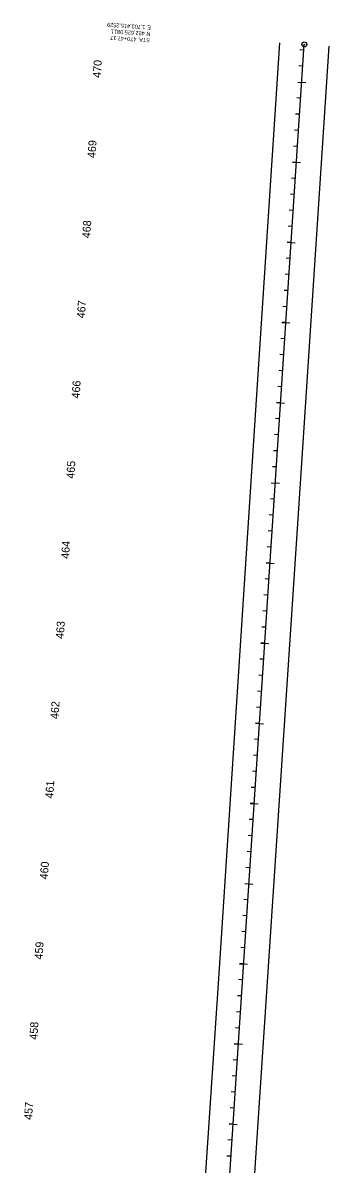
# Model space of a CAD drawing. Extents: x 1699999 to 1705087, y 475568 to 482652.
# Drawn here: x 1703065 to 1703446, y 481231 to 482652 of the extents above; entities that cross this region are included whole.
import ezdxf

# ---------------------------------------------------------------- set-up
doc = ezdxf.new("R2010")
doc.units = 0
for name, color, linetype in [('Default', 7, 'Continuous'), ('DES - DTM - Ground', 7, 'Continuous'), ('DES - DTM - Points - High', 7, 'Continuous'), ('DESIGN - TYPICAL - Guardrail', 7, 'Continuous'), ('TC_Aggregate', 7, 'Continuous')]:
    doc.layers.add(name, color=color, linetype=linetype)

msp = doc.modelspace()

# ---------------------------------------------------------------- linework, layer by layer
at = {"layer": 'Default'}
msp.add_line((1703065.1, 477316.2), (1703415.3, 482625.1), dxfattribs=at)
at = {"layer": 'DES - DTM - Ground'}
msp.add_line((1703065.1, 477316.2), (1703415.3, 482625.1), dxfattribs=at)
for points in [[(1703182.2, 479545.9), (1703224.8, 480202.3), (1703257.7, 480700.5), (1703309.7, 481474.6), (1703350.7, 482106.4), (1703384.7, 482627.1)], [(1703259.7, 479798.3), (1703310.9, 480575.7), (1703327.5, 480825.1), (1703410, 482072.1), (1703446.2, 482623)]]:
    msp.add_lwpolyline(points, dxfattribs=at)
at = {"layer": 'DES - DTM - Points - High'}
for p, q in [((1703414.8, 482617.9), (1703409.8, 482618.3)), ((1703413.5, 482598), (1703408.5, 482598.3)), ((1703407.2, 482578.3), (1703417.1, 482577.7)), ((1703410.8, 482558.1), (1703405.9, 482558.4)), ((1703409.5, 482538.1), (1703404.5, 482538.4)), ((1703408.2, 482518.1), (1703403.2, 482518.5)), ((1703406.9, 482498.2), (1703401.9, 482498.5)), ((1703400.6, 482478.6), (1703410.6, 482477.9)), ((1703404.2, 482458.3), (1703399.3, 482458.6)), ((1703402.9, 482438.3), (1703398, 482438.6)), ((1703401.6, 482418.4), (1703396.6, 482418.7)), ((1703400.3, 482398.4), (1703395.3, 482398.7)), ((1703394, 482378.8), (1703404, 482378.1)), ((1703397.7, 482358.5), (1703392.7, 482358.8)), ((1703396.4, 482338.5), (1703391.4, 482338.9)), ((1703395, 482318.6), (1703390.1, 482318.9)), ((1703393.7, 482298.6), (1703388.7, 482298.9)), ((1703387.4, 482279), (1703397.4, 482278.3)), ((1703391.1, 482258.7), (1703386.1, 482259)), ((1703389.8, 482238.7), (1703384.8, 482239.1)), ((1703388.5, 482218.8), (1703383.5, 482219.1)), ((1703387.1, 482198.8), (1703382.2, 482199.2)), ((1703380.8, 482179.2), (1703390.8, 482178.5)), ((1703384.5, 482158.9), (1703379.5, 482159.2)), ((1703383.2, 482139), (1703378.2, 482139.3)), ((1703381.9, 482119), (1703376.9, 482119.3)), ((1703380.6, 482099.1), (1703375.6, 482099.4)), ((1703374.2, 482079.4), (1703384.2, 482078.8)), ((1703377.9, 482059.1), (1703373, 482059.5)), ((1703376.6, 482039.2), (1703371.6, 482039.5)), ((1703375.3, 482019.2), (1703370.3, 482019.6)), ((1703374, 481999.3), (1703369, 481999.6)), ((1703367.7, 481979.6), (1703377.6, 481979)), ((1703371.3, 481959.4), (1703366.4, 481959.7)), ((1703370, 481939.4), (1703365.1, 481939.7)), ((1703368.7, 481919.4), (1703363.7, 481919.8)), ((1703367.4, 481899.5), (1703362.4, 481899.8)), ((1703361.1, 481879.9), (1703371.1, 481879.2)), ((1703364.8, 481859.6), (1703359.8, 481859.9)), ((1703363.4, 481839.6), (1703358.5, 481839.9)), ((1703362.1, 481819.7), (1703357.2, 481820)), ((1703360.8, 481799.7), (1703355.8, 481800)), ((1703354.5, 481780.1), (1703364.5, 481779.4)), ((1703358.2, 481759.8), (1703353.2, 481760.1)), ((1703356.9, 481739.8), (1703351.9, 481740.2)), ((1703355.5, 481719.9), (1703350.6, 481720.2)), ((1703354.2, 481699.9), (1703349.3, 481700.2)), ((1703347.9, 481680.3), (1703357.9, 481679.6)), ((1703351.6, 481660), (1703346.6, 481660.3)), ((1703350.3, 481640), (1703345.3, 481640.4)), ((1703349, 481620.1), (1703344, 481620.4)), ((1703347.6, 481600.1), (1703342.7, 481600.5)), ((1703341.3, 481580.5), (1703351.3, 481579.8)), ((1703345, 481560.2), (1703340, 481560.6)), ((1703343.7, 481540.3), (1703338.7, 481540.6)), ((1703342.4, 481520.3), (1703337.4, 481520.6)), ((1703341.1, 481500.4), (1703336.1, 481500.7)), ((1703334.8, 481480.7), (1703344.7, 481480.1)), ((1703338.4, 481460.4), (1703333.5, 481460.8)), ((1703337.1, 481440.5), (1703332.1, 481440.8)), ((1703335.8, 481420.5), (1703330.8, 481420.9)), ((1703334.5, 481400.6), (1703329.5, 481400.9)), ((1703328.2, 481380.9), (1703338.2, 481380.3)), ((1703331.8, 481360.7), (1703326.9, 481361)), ((1703330.5, 481340.7), (1703325.6, 481341)), ((1703329.2, 481320.7), (1703324.2, 481321.1)), ((1703327.9, 481300.8), (1703322.9, 481301.1)), ((1703321.6, 481281.2), (1703331.6, 481280.5)), ((1703325.3, 481260.9), (1703320.3, 481261.2)), ((1703323.9, 481240.9), (1703319, 481241.2))]:
    msp.add_line(p, q, dxfattribs=at)
at = {"layer": 'DESIGN - TYPICAL - Guardrail'}
for p, q in [((1703407.2, 482578.3), (1703417.2, 482577.7)), ((1703405.6, 482478.2), (1703400.6, 482478.6)), ((1703399, 482378.4), (1703394, 482378.8)), ((1703392.4, 482278.7), (1703387.4, 482279)), ((1703385.8, 482178.9), (1703380.8, 482179.2)), ((1703374.2, 482079.4), (1703384.2, 482078.8)), ((1703372.7, 481979.3), (1703367.7, 481979.6)), ((1703366.1, 481879.5), (1703361.1, 481879.9)), ((1703359.5, 481779.7), (1703354.5, 481780.1)), ((1703352.9, 481680), (1703347.9, 481680.3)), ((1703341.3, 481580.5), (1703351.3, 481579.8)), ((1703339.7, 481480.4), (1703334.8, 481480.7)), ((1703333.2, 481380.6), (1703328.2, 481380.9)), ((1703326.6, 481280.8), (1703321.6, 481281.2))]:
    msp.add_line(p, q, dxfattribs=at)
for radius in [3.14, 0.33]:
    msp.add_circle((1703415.3, 482625.1), radius, dxfattribs=at)

# ---------------------------------------------------------------- texts
at = {"layer": 'DES - DTM - Points - High'}
for s, p in [('470', (1703161.9, 482583.2)), ('469', (1703155.4, 482483.4)), ('468', (1703148.8, 482383.6)), ('467', (1703142.2, 482283.9)), ('466', (1703135.6, 482184.1)), ('465', (1703129, 482084.2)), ('464', (1703122.5, 481984.5)), ('463', (1703115.9, 481884.7)), ('462', (1703109.3, 481785)), ('461', (1703102.8, 481686.1)), ('460', (1703096.1, 481585.4)), ('459', (1703089.5, 481485.6)), ('458', (1703083, 481385.8)), ('457', (1703076.4, 481286))]:
    msp.add_text(s, height=9.96, rotation=86.2259, dxfattribs=at).set_placement(p)
at = {"layer": 'DESIGN - TYPICAL - Guardrail'}
for s, p in [('470', (1703161.9, 482583.2)), ('465', (1703129, 482084.2)), ('460', (1703096.1, 481585.4))]:
    msp.add_text(s, height=9.96, rotation=86.2259, dxfattribs=at).set_placement(p)
at = {"layer": 'TC_Aggregate'}
for s, p in [('1,703,415.2529', (1703217.8, 482648.9)), ('482,625.0811', (1703216.9, 482641)), ('N ', (1703223.9, 482640.5)), ('E ', (1703224.4, 482648.5)), ('470+47.17', (1703206.5, 482633.7)), ('STA. ', (1703223.3, 482632.6))]:
    msp.add_text(s, height=4.98, rotation=176.2259, dxfattribs=at).set_placement(p)

doc.saveas('drawing.dxf')
